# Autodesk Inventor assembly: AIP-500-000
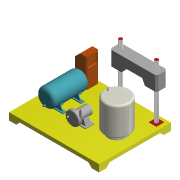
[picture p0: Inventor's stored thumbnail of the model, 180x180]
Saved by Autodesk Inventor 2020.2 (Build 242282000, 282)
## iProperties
Created: 2014-06
Part Number: AIP-500-000
Document SubType Name: Assembly
Designer: F.Stasiak
Catalog Web Link: www.expertbooks.pl
Manager: www.cadconsulting.pl
Company: Fabian Stasiak CAD Consulting
Author: F.Stasiak
Subject: Zbiór ćwiczeń. Autodesk Inventor 2020. Kurs Professional
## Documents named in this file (10)
- C:\2020_Kurs_Professional\R1 Rury\AIP-500-000.iam
- C:\2020_Kurs_Professional\R1 Rury\Platforma.ipt
- C:\2020_Kurs_Professional\R1 Rury\AIP-500-001.ipt
- C:\2020_Kurs_Professional\R1 Rury\AIP-500-002.ipt
- C:\2020_Kurs_Professional\R1 Rury\AIP-Pompa_100.ipt
- C:\2020_Kurs_Professional\R1 Rury\AIP-500-003.ipt
- C:\2020_Kurs_Professional\R1 Rury\AIP-500-004.ipt
- C:\2020_Kurs_Professional\R1 Rury\AIP-500-005.ipt
- C:\2020_Kurs_Professional\Zasoby\ContentCenter\pl-PL\ASME B16.11(22)\ASME B16.11 Tuleja z łbem sześciokątnym 3_4 x 1_2.ipt
- C:\2020_Kurs_Professional\Zasoby\ContentCenter\pl-PL\ASME B16.18(04)\ASME B16.18 Złączka nakrętna C x C 1_2.ipt
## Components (12 placed, 9 different names)
1. Platforma:1 — Zestawiający:1, Zestawiający:2, Zestawiający:3, Zestawiający:4, Zestawiający:5, Równoległy:4, Zestawiający:7, Równoległy:6, Równoległy:7, Równoległy:8, Równoległy:9, Równoległy:10
2. AIP-500-001:1 — Równoległy:1, Zestawiający:1, Zestawiający:2, Równoległy:3, Wstaw:1
3. AIP-500-002:1 — Zestawiający:3, Równoległy:2, Zestawiający:4, Wstaw:5
4. AIP-Pompa_100:1 — Zestawiający:5, Zestawiający:6, Równoległy:3, Wstaw:2, Wstaw:6
5. AIP-500-003:1 — Równoległy:4, Równoległy:5, Równoległy:6, Równoległy:7, Zestawiający:8, Zestawiający:9
6. AIP-500-003:2 — Zestawiający:7, Równoległy:5, Zestawiający:8, Zestawiający:10
7. AIP-500-004:1 — Zestawiający:9, Zestawiający:10
8. AIP-500-005:1 — Równoległy:8, Równoległy:9, Równoległy:10
9. ASME B16.11 Tuleja z łbem sześciokątnym 3/4 x 1/2:1 — Wstaw:1
10. ASME B16.11 Tuleja z łbem sześciokątnym 3/4 x 1/2:2 — Wstaw:2
11. ASME B16.18 Złączka nakrętna C x C 1/2:1 — Wstaw:6
12. ASME B16.18 Złączka nakrętna C x C 1/2:2 — Wstaw:5
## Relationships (24: Flush 10, Mate 10, Insert 4)
- Równoległy:1 [Flush]: AIP-500-001:1
- Zestawiający:1 [Mate]: Platforma:1 ↔ AIP-500-001:1
- Zestawiający:2 [Mate]: Platforma:1 ↔ AIP-500-001:1
- Zestawiający:3 [Mate]: Platforma:1 ↔ AIP-500-002:1
- Równoległy:2 [Flush]: AIP-500-002:1
- Zestawiający:4 [Mate]: Platforma:1 ↔ AIP-500-002:1
- Zestawiający:5 [Mate]: Platforma:1 ↔ AIP-Pompa_100:1
- Zestawiający:6 [Mate]: AIP-Pompa_100:1
- Równoległy:3 [Flush]: AIP-500-001:1 ↔ AIP-Pompa_100:1
- Równoległy:4 [Flush]: Platforma:1 ↔ AIP-500-003:1
- Zestawiający:7 [Mate]: Platforma:1 ↔ AIP-500-003:2
- Równoległy:5 [Flush]: AIP-500-003:1 ↔ AIP-500-003:2
- Równoległy:6 [Flush]: Platforma:1 ↔ AIP-500-003:1
- Równoległy:7 [Flush]: Platforma:1 ↔ AIP-500-003:1
- Zestawiający:8 [Mate]: AIP-500-003:1 ↔ AIP-500-003:2
- Zestawiający:9 [Mate]: AIP-500-003:1 ↔ AIP-500-004:1
- Zestawiający:10 [Mate]: AIP-500-003:2 ↔ AIP-500-004:1
- Równoległy:8 [Flush]: Platforma:1 ↔ AIP-500-005:1
- Równoległy:9 [Flush]: Platforma:1 ↔ AIP-500-005:1
- Równoległy:10 [Flush]: Platforma:1 ↔ AIP-500-005:1
- Wstaw:1 [Insert]: AIP-500-001:1 ↔ ASME B16.11 Tuleja z łbem sześciokątnym 3/4 x 1/2:1
- Wstaw:2 [Insert]: AIP-Pompa_100:1 ↔ ASME B16.11 Tuleja z łbem sześciokątnym 3/4 x 1/2:2
- Wstaw:5 [Insert]: AIP-500-002:1 ↔ ASME B16.18 Złączka nakrętna C x C 1/2:2
- Wstaw:6 [Insert]: AIP-Pompa_100:1 ↔ ASME B16.18 Złączka nakrętna C x C 1/2:1
